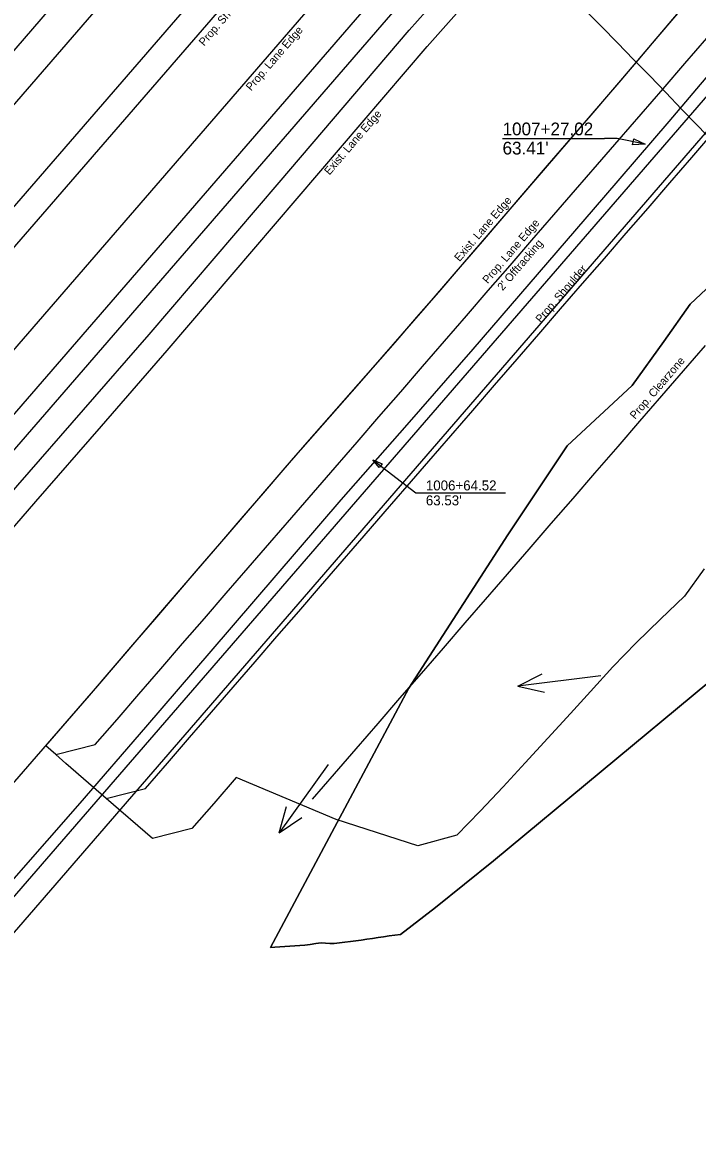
# Model space of a CAD drawing. Extents: x 1006695 to 1009377, y 1883329 to 1886115.
# Drawn here: x 1007827 to 1007928.2, y 1884510 to 1884679.4 of the extents above; entities that cross this region are included whole.
import ezdxf

# ---------------------------------------------------------------- set-up
doc = ezdxf.new("R2010")
doc.units = 0
for name, color, linetype in [('B_Hatch', 7, 'Continuous'), ('R_I-30 Information', 7, 'Continuous'), ('R_No Plot', 7, 'Continuous'), ('R_Prop Const Limits Cut', 7, 'Continuous'), ('R_Prop EOL', 7, 'Continuous'), ('R_Prop EOS I-30', 7, 'Continuous'), ('R_Prop I-30 Guardrail', 7, 'Continuous'), ('R_Water Annot', 7, 'Continuous')]:
    doc.layers.add(name, color=color, linetype=linetype)

msp = doc.modelspace()

# ---------------------------------------------------------------- linework, layer by layer
at = {"layer": 'B_Hatch'}
msp.add_lwpolyline([(1007931.9, 1884641.74), (1007927.14, 1884637.26), (1007923.15, 1884631.63), (1007918.41, 1884625.07), (1007908.67, 1884616.02), (1007899.79, 1884602.67), (1007884.94, 1884579.7), (1007864.21, 1884540.79), (1007864.84, 1884540.84), (1007865.59, 1884540.9), (1007866.34, 1884540.96), (1007867.09, 1884541.01), (1007867.84, 1884541.07), (1007868.59, 1884541.12), (1007869.34, 1884541.17), (1007870.15, 1884541.28), (1007871.01, 1884541.43), (1007871.8, 1884541.51), (1007872.44, 1884541.47), (1007873.09, 1884541.43), (1007873.75, 1884541.4), (1007874.55, 1884541.5), (1007875.36, 1884541.6), (1007876.17, 1884541.7), (1007876.98, 1884541.8), (1007877.81, 1884541.92), (1007878.64, 1884542.05), (1007879.48, 1884542.17), (1007880.32, 1884542.29), (1007881.16, 1884542.41), (1007882, 1884542.54), (1007882.83, 1884542.66), (1007883.67, 1884542.77), (1007888.95, 1884546.79), (1007897.65, 1884553.78), (1007929.93, 1884580.6)], dxfattribs=at)
at = {"layer": 'R_I-30 Information'}
for p, q in [((1007780.22, 1884614.59), (1007976.64, 1884841.35)), ((1007787.78, 1884608.04), (1007984.2, 1884834.8)), ((1007790.8, 1884605.42), (1007987.22, 1884832.18)), ((1007798.36, 1884598.88), (1007994.78, 1884825.63))]:
    msp.add_line(p, q, dxfattribs=at)
for points in [[(1007740.78, 1884505.63), (1007750.62, 1884516.95), (1007760.46, 1884528.27), (1007770.23, 1884539.51), (1007780.07, 1884550.83), (1007789.88, 1884562.17), (1007799.65, 1884573.56), (1007809.41, 1884584.94), (1007819.18, 1884596.32), (1007829.02, 1884607.64), (1007838.86, 1884618.96), (1007848.7, 1884630.28), (1007858.47, 1884641.66), (1007868.2, 1884653.07), (1007887.67, 1884675.88), (1007897.62, 1884687.1)], [(1007769.41, 1884500.69), (1007779.21, 1884512.04), (1007789.07, 1884523.47), (1007798.87, 1884534.82), (1007808.73, 1884546.12), (1007818.61, 1884557.41), (1007828.48, 1884568.7), (1007838.31, 1884580.03), (1007848.08, 1884591.4), (1007857.85, 1884602.78), (1007867.63, 1884614.15), (1007877.53, 1884625.42), (1007887.41, 1884636.7), (1007906.97, 1884659.44), (1007916.75, 1884670.81), (1007926.47, 1884682.23)], [(1007929.21, 1884597.56), (1007926.27, 1884593.49), (1007922.65, 1884590.01), (1007919.03, 1884586.46), (1007915.54, 1884582.87), (1007912.16, 1884579.18), (1007909.16, 1884575.89), (1007905.78, 1884572.2), (1007902.4, 1884568.51), (1007899.09, 1884564.87), (1007895.62, 1884561.25), (1007892.13, 1884557.66), (1007886.3, 1884556.07), (1007874.05, 1884560), (1007859.04, 1884566.3), (1007855.7, 1884562.41), (1007852.41, 1884558.65), (1007846.49, 1884557.17), (1007839.57, 1884563.17), (1007833.53, 1884568.41), (1007832.02, 1884569.72), (1007830.51, 1884571.03), (1007833.78, 1884574.81), (1007837.06, 1884578.58), (1007840.32, 1884582.37), (1007843.58, 1884586.16), (1007846.84, 1884589.96), (1007850.09, 1884593.75), (1007853.35, 1884597.55), (1007856.61, 1884601.34), (1007859.87, 1884605.13), (1007863.13, 1884608.92), (1007866.39, 1884612.71), (1007869.68, 1884616.48), (1007872.98, 1884620.23), (1007876.28, 1884623.99), (1007879.57, 1884627.75), (1007882.87, 1884631.51), (1007886.16, 1884635.27), (1007889.44, 1884639.05), (1007892.7, 1884642.84), (1007895.96, 1884646.63), (1007899.22, 1884650.42), (1007902.48, 1884654.21), (1007905.74, 1884658), (1007909, 1884661.79), (1007912.26, 1884665.58), (1007915.52, 1884669.38), (1007918.77, 1884673.18), (1007922.01, 1884676.99), (1007925.25, 1884680.8)], [(1007832.02, 1884569.72), (1007837.91, 1884571.23), (1007841.19, 1884575), (1007844.48, 1884578.8), (1007847.75, 1884582.58), (1007851.02, 1884586.36), (1007854.3, 1884590.14), (1007857.57, 1884593.92), (1007860.85, 1884597.7), (1007864.11, 1884601.47), (1007867.39, 1884605.25), (1007870.66, 1884609.03), (1007873.9, 1884612.77), (1007877.17, 1884616.55), (1007880.45, 1884620.33), (1007883.72, 1884624.11), (1007887, 1884627.89), (1007890.27, 1884631.67), (1007893.58, 1884635.49), (1007896.85, 1884639.27), (1007900.12, 1884643.05), (1007903.4, 1884646.83), (1007906.67, 1884650.61), (1007909.95, 1884654.39), (1007913.22, 1884658.17), (1007916.49, 1884661.94), (1007919.77, 1884665.72), (1007923.06, 1884669.53), (1007926.34, 1884673.31), (1007929.61, 1884677.09)], [(1007839.57, 1884563.17), (1007845.47, 1884564.67), (1007848.74, 1884568.45), (1007852.06, 1884572.29), (1007855.34, 1884576.07), (1007858.61, 1884579.85), (1007861.88, 1884583.63), (1007865.16, 1884587.41), (1007868.43, 1884591.19), (1007871.69, 1884594.95), (1007874.96, 1884598.73), (1007878.24, 1884602.51), (1007881.41, 1884606.17), (1007884.69, 1884609.95), (1007887.96, 1884613.73), (1007891.25, 1884617.52), (1007894.52, 1884621.3), (1007897.79, 1884625.08), (1007901.16, 1884628.97), (1007904.43, 1884632.75), (1007907.7, 1884636.53), (1007910.98, 1884640.31), (1007914.25, 1884644.08), (1007917.53, 1884647.86), (1007920.8, 1884651.64), (1007924.07, 1884655.42), (1007927.35, 1884659.2), (1007930.68, 1884663.05)], [(1007870.51, 1884563.04), (1007873.78, 1884566.82), (1007877.06, 1884570.6), (1007880.33, 1884574.38), (1007883.61, 1884578.16), (1007886.85, 1884581.9), (1007890.12, 1884585.68), (1007893.39, 1884589.46), (1007896.44, 1884592.98), (1007899.72, 1884596.76), (1007902.99, 1884600.54), (1007906.29, 1884604.35), (1007909.56, 1884608.12), (1007912.84, 1884611.9), (1007916.32, 1884615.92), (1007919.59, 1884619.7), (1007922.87, 1884623.48), (1007926.14, 1884627.26), (1007929.41, 1884631.04)]]:
    msp.add_lwpolyline(points, dxfattribs=at)
at = {"layer": 'R_No Plot'}
for p, q in [((1007898.99, 1884662.06), (1007914.27, 1884662.06)), ((1007887.49, 1884608.94), (1007899.42, 1884608.94))]:
    msp.add_line(p, q, dxfattribs=at)
for points in [[(1007920.39, 1884661.23), (1007916.18, 1884662.06), (1007914.27, 1884662.06)], [(1007879.55, 1884613.91), (1007885.99, 1884608.94), (1007887.49, 1884608.94)]]:
    msp.add_lwpolyline(points, dxfattribs=at)
for points in [[(1007920.39, 1884661.23), (1007918.47, 1884661.13), (1007918.65, 1884662.04)], [(1007879.55, 1884613.91), (1007880.92, 1884613.31), (1007880.48, 1884612.74)]]:
    msp.add_lwpolyline(points, close=True, dxfattribs=at)
at = {"layer": 'R_Prop Const Limits Cut'}
msp.add_lwpolyline([(1007929.93, 1884580.6), (1007897.65, 1884553.78), (1007888.95, 1884546.79), (1007883.67, 1884542.77), (1007882.83, 1884542.66), (1007882, 1884542.54), (1007881.16, 1884542.41), (1007880.32, 1884542.29), (1007879.48, 1884542.17), (1007878.64, 1884542.05), (1007877.81, 1884541.92), (1007876.98, 1884541.8), (1007876.17, 1884541.7), (1007875.36, 1884541.6), (1007874.55, 1884541.5), (1007873.75, 1884541.4), (1007873.09, 1884541.43), (1007872.44, 1884541.47), (1007871.8, 1884541.51), (1007871.01, 1884541.43), (1007870.15, 1884541.28), (1007869.34, 1884541.17), (1007868.59, 1884541.12), (1007867.84, 1884541.07), (1007867.09, 1884541.01), (1007866.34, 1884540.96), (1007865.59, 1884540.9), (1007864.84, 1884540.84), (1007864.21, 1884540.79), (1007884.94, 1884579.7), (1007899.79, 1884602.67), (1007908.67, 1884616.02), (1007918.41, 1884625.07), (1007923.15, 1884631.63), (1007927.14, 1884637.26), (1007931.9, 1884641.74)], dxfattribs=at)
at = {"layer": 'R_Prop EOL'}
for radius, start in [(1443.39, 37.04506), (1421.39, 35.65164)]:
    msp.add_arc((1006901.08, 1883681.49), radius, start, 53.47197, dxfattribs=at)
at = {"layer": 'R_Prop EOS I-30'}
for p, q in [((1007789.1, 1884632.79), (1008066.81, 1884954.51)), ((1007648.59, 1884416.23), (1007989.05, 1884809.28)), ((1007713.67, 1884413.61), (1007972.2, 1884712.26))]:
    msp.add_line(p, q, dxfattribs=at)
for points in [[(1007786.4, 1884505.84), (1007796.26, 1884517.26), (1007806.04, 1884528.59), (1007815.89, 1884539.87), (1007825.76, 1884551.15), (1007835.65, 1884562.46), (1007845.5, 1884573.82), (1007855.29, 1884585.22), (1007865.05, 1884596.59), (1007874.8, 1884607.91), (1007884.67, 1884619.16), (1007894.58, 1884630.47), (1007914.18, 1884653.24), (1007923.97, 1884664.63), (1007933.68, 1884676.05), (1007943.28, 1884687.18), (1007953.08, 1884698.54), (1007962.87, 1884709.9), (1007972.64, 1884721.22), (1007988.72, 1884741.6)], [(1007738.1, 1884508.07), (1007747.94, 1884519.39), (1007757.78, 1884530.72), (1007767.55, 1884541.96), (1007777.38, 1884553.27), (1007787.19, 1884564.6), (1007796.95, 1884575.97), (1007806.71, 1884587.36), (1007816.49, 1884598.75), (1007826.34, 1884610.09), (1007836.18, 1884621.4), (1007846.01, 1884632.7), (1007855.77, 1884644.07), (1007865.5, 1884655.48), (1007884.99, 1884678.32), (1007894.96, 1884689.56)]]:
    msp.add_lwpolyline(points, dxfattribs=at)
at = {"layer": 'R_Prop I-30 Guardrail'}
for p, q in [((1007657.79, 1884421.5), (1007985.15, 1884799.43)), ((1007717.57, 1884423.47), (1007963.01, 1884706.99))]:
    msp.add_line(p, q, dxfattribs=at)
at = {"layer": 'R_Water Annot'}
for p, q in [((1007901.27, 1884579.98), (1007904.91, 1884581.85)), ((1007913.74, 1884581.55), (1007901.27, 1884579.98)), ((1007901.27, 1884579.98), (1007905.26, 1884579.07)), ((1007872.83, 1884568.22), (1007865.5, 1884558.02)), ((1007865.5, 1884558.02), (1007866.61, 1884561.96)), ((1007865.5, 1884558.02), (1007868.88, 1884560.32))]:
    msp.add_line(p, q, dxfattribs=at)

# ---------------------------------------------------------------- texts
at = {"layer": 'R_I-30 Information'}
for s, p in [('Prop. Shoulder', (1007854.24, 1884675.84)), ('Prop. Lane Edge', (1007861.29, 1884669.12)), ('Exist. Lane Edge', (1007873.04, 1884656.5)), ('Exist. Lane Edge', (1007892.54, 1884643.53)), ('Prop. Lane Edge', (1007896.77, 1884640.22)), ("2' Offtracking", (1007899, 1884639.17)), ('Prop. Shoulder', (1007904.72, 1884634.34)), ('Prop. Clearzone', (1007918.86, 1884619.91))]:
    msp.add_text(s, height=1.2, rotation=49.3699, dxfattribs=at).set_placement(p)
at = {"layer": 'R_No Plot'}
for s, height, p in [('1007+27.02', 1.914, (1007898.99, 1884662.54)), ("63.41'", 1.914, (1007898.99, 1884659.67)), ('1006+64.52', 1.492, (1007887.49, 1884609.32)), ("63.53'", 1.492, (1007887.49, 1884607.08))]:
    msp.add_text(s, height=height, dxfattribs=at).set_placement(p)

doc.saveas('drawing.dxf')
